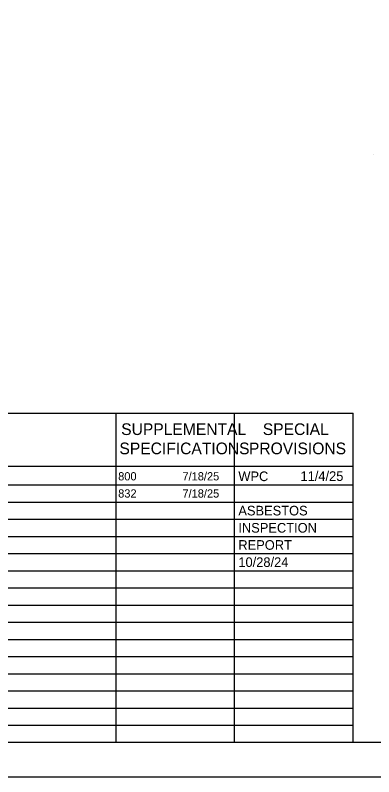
# Model space of a CAD drawing. Extents: x 0 to 34, y 0 to 22.
# Drawn here: x 19.78 to 25, y 0 to 11.09 of the extents above; entities that cross this region are included whole.
import ezdxf

# ---------------------------------------------------------------- set-up
doc = ezdxf.new("R2010")
doc.units = 0
for name, color, linetype in [('GM_X_Adjacent_County', 7, 'Continuous'), ('GM_X_County', 7, 'Continuous'), ('GM_X_Section', 7, 'Continuous'), ('GM_X_Township', 7, 'Continuous')]:
    doc.layers.add(name, color=color, linetype=linetype)

msp = doc.modelspace()

# ---------------------------------------------------------------- linework, layer by layer
at = {"layer": 'GM_X_County'}
msp.add_lwpolyline([(1.5, 21.5), (33.5, 21.5), (33.5, 0.5), (1.5, 0.5)], close=True, dxfattribs=at)
at = {"layer": 'GM_X_Section'}
msp.add_lwpolyline([(0, 0), (34, 0), (34, 22), (0, 22)], close=True, dxfattribs=at)
at = {"layer": 'GM_X_Township'}
for p, q in [((25, 9.06), (25, 9.06)), ((11.25, 5.292), (24.7, 5.292)), ((21.25, 0.5), (21.25, 5.292)), ((22.975, 0.5), (22.975, 5.292)), ((24.7, 0.5), (24.7, 5.292)), ((11.25, 4.521), (24.7, 4.521)), ((11.25, 4.25), (24.7, 4.25)), ((11.25, 4), (24.7, 4)), ((11.25, 3.75), (24.7, 3.75)), ((11.25, 3.5), (24.7, 3.5)), ((11.25, 3.25), (24.7, 3.25)), ((11.25, 3), (24.7, 3)), ((11.25, 2.75), (24.7, 2.75)), ((11.25, 2.5), (24.7, 2.5)), ((11.25, 2.25), (24.7, 2.25)), ((11.25, 2), (24.7, 2)), ((11.25, 1.75), (24.7, 1.75)), ((11.25, 1.5), (24.7, 1.5)), ((11.25, 1.25), (24.7, 1.25)), ((11.25, 1), (24.7, 1)), ((11.25, 0.75), (24.7, 0.75))]:
    msp.add_line(p, q, dxfattribs=at)

# ---------------------------------------------------------------- texts
at = {"layer": 'GM_X_Adjacent_County'}
for s, height, p in [('SUPPLEMENTAL', 0.17, (21.324, 4.976)), ('SPECIAL', 0.17, (23.386, 4.976)), ('SPECIFICATIONS', 0.17, (21.298, 4.696)), ('PROVISIONS', 0.17, (23.184, 4.696)), ('800', 0.12, (21.28, 4.315)), ('7/18/25', 0.12, (22.216, 4.315)), ('WPC', 0.14, (23.03, 4.305)), ('11/4/25', 0.14, (23.935, 4.308)), ('832', 0.12, (21.28, 4.065)), ('7/18/25', 0.12, (22.216, 4.065)), ('ASBESTOS', 0.14, (23.03, 3.805)), ('INSPECTION', 0.14, (23.03, 3.555)), ('REPORT', 0.14, (23.03, 3.305)), ('10/28/24', 0.14, (23.03, 3.055))]:
    msp.add_text(s, height=height, dxfattribs=at).set_placement(p)

doc.saveas('drawing.dxf')
